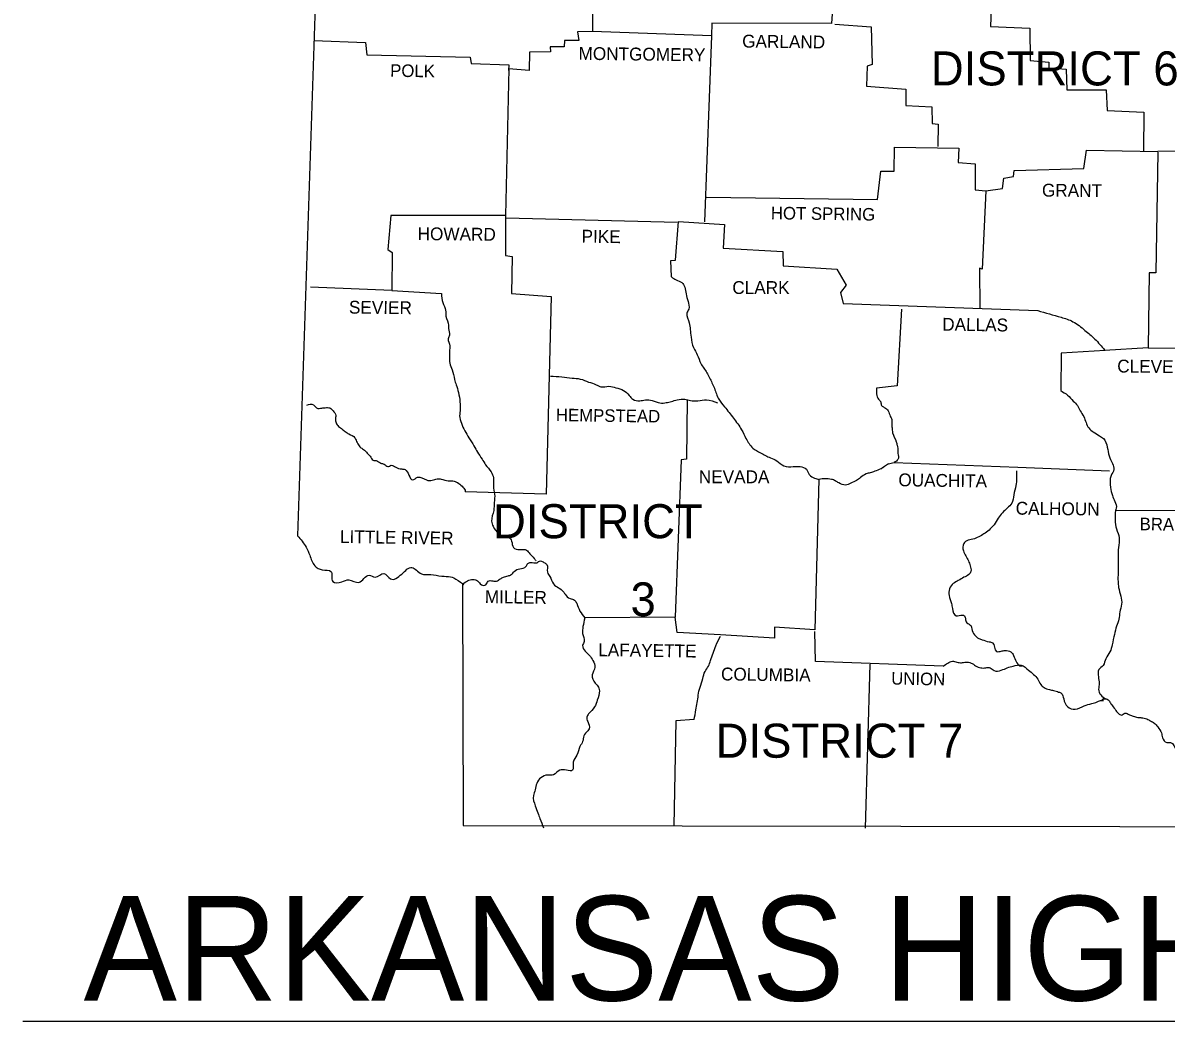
# Model space of a CAD drawing. Extents: x 155 to 3386, y 68 to 2138.
# Drawn here: x 2625.2 to 2999.8, y 1369.4 to 1696.4 of the extents above; entities that cross this region are included whole.
import ezdxf

# ---------------------------------------------------------------- set-up
doc = ezdxf.new("R2010")
doc.units = 0
for name, color, linetype in [('1', 7, 'Continuous'), ('2', 7, 'Continuous'), ('3', 7, 'Continuous')]:
    doc.layers.add(name, color=color, linetype=linetype)

msp = doc.modelspace()

# ---------------------------------------------------------------- linework, layer by layer
at = {"layer": '1'}
for points in [[(2703.71, 1956.42), (2723.96, 1793.81), (2715.15, 1528.37)], [(2812.02, 1750.86), (2811.82, 1693.62), (2806.93, 1693.52), (2807.32, 1690.59), (2802.62, 1690.68), (2802.53, 1688.53), (2797.93, 1688.53), (2798.03, 1686.97), (2791.18, 1686.77), (2791.08, 1680.8), (2784.43, 1681.39), (2783.35, 1633.25), (2745.68, 1633.35), (2744.8, 1622.19), (2746.17, 1621.22), (2746.07, 1608.69), (2719.36, 1609.87)], [(2922.97, 1707.81), (2890.97, 1708.78), (2890.09, 1696.16), (2850.96, 1696.36), (2850.76, 1692.15)], [(2931.68, 1708.1), (2942.63, 1707.41), (2942.24, 1695.18), (2955.06, 1694.69), (2955.26, 1684.03), (2961.32, 1683.54), (2961.32, 1681.68), (2967, 1681.29), (2967.19, 1674.44), (2980.11, 1674.44), (2980.5, 1667.69), (2992.44, 1667.1), (2992.34, 1654.38)], [(2850.76, 1692.15), (2811.82, 1693.62)], [(2891.27, 1695.97), (2903.11, 1695.09), (2903.5, 1682.76), (2901.83, 1682.17), (2901.64, 1675.62), (2914.46, 1674.74), (2914.46, 1669.35), (2922.97, 1668.86), (2923.07, 1663.48), (2925.12, 1663.19), (2925.02, 1655.95)], [(2720.54, 1690.59), (2737.46, 1690), (2737.85, 1685.89), (2771.71, 1685.2), (2772.1, 1683.05), (2784.43, 1682.66), (2784.33, 1680.8)], [(2850.76, 1692.15), (2848.51, 1631.2)], [(3109.06, 1665.64), (3072.08, 1666.61), (3071.88, 1654.58), (2997.03, 1654.29)], [(2849.2, 1639.32), (2905.16, 1638.53), (2906.24, 1647.83), (2910.64, 1647.83), (2910.74, 1655.66), (2931.87, 1655.36), (2931.68, 1650.67), (2937.16, 1650.27), (2937.16, 1641.66), (2940.68, 1641.37)], [(2940.68, 1641.37), (2946.16, 1642.15), (2946.55, 1645.48), (2949.78, 1646.07), (2949.97, 1648.02), (2972.77, 1648.71), (2973.65, 1654.68), (2997.03, 1654.29)], [(2997.03, 1654.09), (2996.45, 1614.56), (2994.2, 1614.47), (2993.9, 1589.91)], [(2940.68, 1641.37), (2939.5, 1615.74), (2938.62, 1616.03), (2938.72, 1602.72)], [(2783.35, 1633.25), (2783.35, 1620.24), (2785.5, 1619.85), (2785.31, 1607.71), (2798.22, 1606.74), (2796.66, 1542.06), (2770.04, 1542.75)], [(2783.55, 1632.57), (2839.51, 1631.1)], [(2837.65, 1613.19), (2837.46, 1618.57), (2839.02, 1618.67), (2840, 1631.29), (2855.07, 1630.32), (2854.68, 1622.59), (2874.15, 1621.51), (2874.24, 1616.81), (2891.85, 1615.74), (2894.89, 1610.45), (2893.03, 1608.11), (2893.91, 1604.49), (2957.7, 1602.14)], [(2746.07, 1608.69), (2762.31, 1607.71)], [(2913.09, 1602.63), (2911.62, 1577.48), (2904.87, 1576.7)], [(2979.81, 1589.03), (2965.33, 1588.15), (2965.24, 1575.92)], [(2993.9, 1589.91), (2979.62, 1589.03)], [(2993.9, 1589.91), (3028.54, 1589.71)], [(2842.84, 1572.98), (2842.64, 1553.51), (2840.88, 1553.31), (2838.92, 1501.75)], [(2910.64, 1552.34), (2951.15, 1550.87), (2981.18, 1549.69)], [(2885.98, 1546.86), (2884.71, 1497.55), (2871.5, 1498.43), (2871.41, 1494.81), (2853.79, 1495.88)], [(2983.14, 1536.68), (3027.36, 1536.78)], [(2769.26, 1512.61), (2769.46, 1433.46), (3128.04, 1432.87)], [(2853.79, 1495.88), (2839.61, 1496.67), (2838.92, 1501.75), (2809.28, 1501.46)], [(2926.69, 1485.61), (2884.91, 1487.17), (2884.71, 1497.06)], [(2902.72, 1486.29), (2901.15, 1432.58)], [(2845.18, 1468.19), (2839.12, 1467.8), (2838.43, 1433.36)]]:
    msp.add_lwpolyline(points, dxfattribs=at)
for points in [[(2837.65, 1613.19), (2839.22, 1612.21), (2841.08, 1611.33), (2842.05, 1609.87), (2842.45, 1607.62), (2843.13, 1605.17), (2843.33, 1602.63), (2842.74, 1601.26), (2843.52, 1598.13), (2843.82, 1595.97), (2844.11, 1593.43), (2844.89, 1590.01), (2846.16, 1587.66), (2847.34, 1584.82), (2849.29, 1581.79), (2850.96, 1578.46), (2851.74, 1576.7), (2853.21, 1573.08), (2855.07, 1570.63), (2858, 1566.91), (2860.64, 1563.1), (2862.11, 1560.26), (2864.36, 1557.13), (2866.91, 1555.57), (2870.13, 1553.9), (2872.19, 1552.92), (2874.54, 1551.26), (2877.57, 1551.06), (2879.82, 1551.06), (2881.88, 1550.18), (2882.85, 1548.42), (2884.61, 1547.25), (2885.98, 1546.86)], [(2762.31, 1607.71), (2762.8, 1604.78), (2763.68, 1602.24), (2763.78, 1600.28), (2764.66, 1597.34), (2764.66, 1596.27), (2764.96, 1594.11), (2764.56, 1592.94), (2765.05, 1590.59), (2764.96, 1588.83), (2764.96, 1587.36), (2765.05, 1584.92), (2765.84, 1582.76), (2766.62, 1579.54), (2767.11, 1577.87), (2767.89, 1575.33), (2768.38, 1572.2), (2768.48, 1569.85), (2768.28, 1567.7), (2768.87, 1565.25), (2769.95, 1562.81), (2771.32, 1560.46), (2772.98, 1557.82), (2774.15, 1555.76), (2775.62, 1553.51), (2776.79, 1551.65), (2778.56, 1549.3), (2779.34, 1547.35), (2779.34, 1544.61), (2779.73, 1542.06), (2779.63, 1539.23), (2779.44, 1536.68), (2778.75, 1533.16), (2779.24, 1531.5), (2781.1, 1529.05), (2782.27, 1528.37), (2784.33, 1527.97), (2785.31, 1526.6), (2785.89, 1524.55), (2787.95, 1523.86), (2790.2, 1523.67), (2791.27, 1522.49), (2792.74, 1520.93), (2793.23, 1520.15)], [(2957.7, 1602.14), (2965.33, 1599.98), (2969.25, 1598.52), (2973.16, 1595.68), (2976.39, 1592.84), (2979.62, 1589.22)], [(2798.03, 1580.71), (2801.74, 1580.42), (2805.17, 1580.03), (2807.81, 1579.73), (2810.55, 1578.75), (2813, 1577.87), (2814.56, 1577.19), (2817.2, 1577.38), (2819.45, 1576.89), (2822, 1576.01), (2823.86, 1574.35), (2825.03, 1573.08), (2827.28, 1572.59), (2829.14, 1572.88), (2831.39, 1572.69), (2833.93, 1571.9), (2835.99, 1572), (2837.65, 1572.39), (2839.61, 1572.88), (2842.05, 1573.08), (2843.91, 1572.69), (2846.36, 1572.59), (2849.2, 1572.88), (2852.72, 1571.9)], [(2904.87, 1576.7), (2904.87, 1574.84), (2905.55, 1573.08), (2906.24, 1572.3), (2906.53, 1571.02), (2907.41, 1570.44), (2908.68, 1569.26), (2909.37, 1567.6), (2909.86, 1566.52), (2909.86, 1565.15), (2909.96, 1563.78), (2910.15, 1562.12), (2911.33, 1559.19), (2911.62, 1558.01), (2911.81, 1557.03), (2911.91, 1555.37), (2911.91, 1553.41), (2910.64, 1552.34)], [(2965.24, 1575.92), (2967.49, 1574.45), (2969.34, 1572.49), (2970.71, 1571.02), (2971.59, 1569.36), (2972.77, 1567.4), (2974.43, 1563.69), (2975.9, 1562.41), (2977.95, 1561.14), (2979.23, 1560.26), (2980.5, 1557.42), (2981.09, 1554.59), (2982.16, 1552.04), (2982.65, 1550.09), (2981.77, 1548.13), (2981.57, 1544.22), (2982.16, 1541.57), (2982.94, 1539.62), (2983.43, 1537.37), (2983.14, 1536.68)], [(2718.19, 1571.22), (2720.34, 1571.32), (2721.81, 1570.05), (2722.69, 1570.14), (2724.25, 1570.34), (2725.72, 1570.24), (2726.8, 1569.36), (2727.68, 1567.8), (2727.58, 1566.33), (2727.68, 1565.74), (2728.36, 1564.47), (2729.54, 1563.49), (2730.81, 1562.51), (2731.98, 1561.73), (2733.94, 1560.46), (2734.14, 1560.07), (2734.92, 1558.5), (2735.9, 1557.23), (2737.07, 1556.45), (2738.34, 1555.08), (2738.93, 1554.49), (2739.91, 1553.12), (2740.98, 1553.02), (2742.45, 1552.14), (2743.53, 1551.85), (2744.7, 1551.06), (2745.88, 1551.46), (2747.34, 1550.87), (2749.3, 1550.28), (2750.38, 1550.09), (2751.65, 1548.23), (2752.92, 1546.66), (2754.49, 1547.54), (2757.42, 1546.66), (2759.28, 1546.56), (2760.94, 1547.05), (2762.22, 1546.96), (2764.56, 1546.37), (2766.03, 1546.37), (2767.6, 1545.78), (2769.06, 1544.61), (2770.04, 1543.34), (2770.04, 1542.75)], [(2908.78, 1551.95), (2906.24, 1550.28), (2904.28, 1549.5), (2902.81, 1549.01), (2901.44, 1548.62), (2899.68, 1547.44), (2898.31, 1546.47), (2896.45, 1545.59), (2894.69, 1545), (2892.54, 1545.68), (2891.37, 1546.37), (2890.09, 1546.86), (2885.98, 1546.86)], [(2906.24, 1550.28), (2908.78, 1551.95), (2910.64, 1552.34)], [(2950.75, 1549.69), (2950.56, 1544.8), (2949.87, 1541.77), (2949.19, 1539.03), (2947.72, 1537.46), (2946.16, 1535.9), (2944.69, 1534.14), (2943.42, 1531.99), (2942.14, 1530.62), (2940.48, 1529.25), (2938.82, 1528.27), (2936.96, 1527.39), (2934.9, 1526.9), (2933.44, 1525.82), (2933.34, 1523.47), (2935, 1520.15), (2935.59, 1518.58), (2935.79, 1516.72), (2935.1, 1515.65), (2933.53, 1514.77), (2931.68, 1513.69), (2930.01, 1512.71), (2928.84, 1511.05), (2928.64, 1508.8), (2929.43, 1506.16), (2929.72, 1504.59), (2930.99, 1502.14), (2931.97, 1502.24), (2933.73, 1502.14), (2933.93, 1501.65), (2934.02, 1501.17), (2934.42, 1499.89), (2935.88, 1498.82), (2936.08, 1497.84), (2936.96, 1495.98), (2938.43, 1494.71), (2939.5, 1494.32), (2941.75, 1493.63), (2942.93, 1493.34), (2944.2, 1490.5), (2945.77, 1490.6), (2946.94, 1490.79), (2948.9, 1490.31), (2949.78, 1489.13), (2950.66, 1487.17), (2951.83, 1485.8), (2952.61, 1485.8)], [(2983.14, 1536.68), (2983.53, 1530.62), (2984.41, 1527.68), (2984.12, 1524.55), (2984.02, 1521.52), (2984.02, 1518.78), (2984.02, 1516.14), (2984.02, 1513.4), (2984.22, 1511.44), (2984.9, 1508.6), (2985.19, 1505.96), (2984.61, 1503.42), (2984.31, 1501.07), (2983.53, 1498.72), (2982.85, 1496.08), (2982.06, 1492.65), (2981.38, 1490.4), (2980.01, 1488.06), (2979.13, 1485.9), (2977.76, 1484.53), (2977.56, 1482.18), (2977.86, 1480.03), (2977.66, 1478.08), (2978.35, 1476.22), (2980.11, 1474.94)], [(2715.15, 1528.37), (2717.99, 1524.65), (2719.17, 1522.01), (2720.83, 1518.58), (2723.28, 1517.21), (2726.11, 1516.72), (2726.7, 1513.4), (2729.63, 1513.3), (2731.98, 1513.98), (2735.21, 1513.1), (2738.64, 1515.45), (2740.59, 1514.86), (2743.43, 1516.04), (2745.58, 1514.28), (2749.3, 1515.84), (2752.63, 1517.99), (2755.76, 1515.94), (2758.79, 1515.65), (2762.41, 1515.16), (2765.25, 1514.96), (2767.79, 1513.69), (2769.65, 1512.42), (2769.26, 1512.61)], [(2769.26, 1512.61), (2772.68, 1514.08), (2774.15, 1513.59), (2775.42, 1512.32), (2776.89, 1512.32), (2777.67, 1513.49), (2779.14, 1513.59), (2780.32, 1513.49), (2781.59, 1514.28), (2782.66, 1514.77), (2784.13, 1515.25), (2785.21, 1515.65), (2786.19, 1516.72), (2787.95, 1517.6), (2790, 1518.29), (2790.59, 1519.27), (2791.57, 1519.66), (2793.52, 1519.56), (2794.8, 1520.15), (2795.87, 1519.66), (2796.85, 1518.97), (2797.05, 1516.43), (2797.83, 1515.06), (2799, 1512.61), (2800.67, 1511.34), (2802.23, 1510.07), (2802.82, 1509.29), (2804.48, 1507.82), (2805.95, 1507.33), (2806.64, 1506.25), (2807.71, 1503.71), (2809.28, 1501.46)], [(2809.28, 1501.46), (2808.69, 1498.62), (2808.59, 1496.37), (2809.08, 1493.73), (2808.59, 1492.46), (2809.38, 1490.6), (2810.84, 1489.13), (2811.92, 1487.57), (2812.6, 1485.32), (2811.72, 1482.77), (2812.7, 1480.13), (2813.58, 1479.15), (2814.07, 1477.59), (2813.39, 1474.55), (2812.51, 1472.3), (2810.55, 1470.05), (2809.96, 1468.98), (2810.26, 1467.51), (2810.74, 1465.16), (2810.26, 1464.48), (2808.98, 1462.81), (2808.59, 1460.95), (2807.71, 1459.39), (2806.73, 1456.55), (2805.46, 1454.2), (2805.27, 1451.56), (2803.31, 1451.56), (2801.06, 1451.56), (2799, 1450.09), (2797.15, 1450), (2794.89, 1449.11), (2793.52, 1447.26), (2793.04, 1445.2), (2792.45, 1443.24), (2793.04, 1439.92), (2793.92, 1437.57), (2794.6, 1435.71), (2795.78, 1432.68)], [(2845.18, 1468.19), (2845.67, 1471.32), (2846.16, 1473.77), (2846.46, 1476.12), (2847.04, 1478.76), (2847.92, 1481.6), (2848.71, 1483.95), (2849.78, 1485.61), (2850.47, 1487.57), (2851.35, 1489.91), (2852.23, 1492.36), (2853.79, 1495.49)], [(2926.69, 1485.61), (2928.25, 1486.69), (2929.72, 1487.27), (2931.19, 1486.98), (2932.75, 1486.78), (2934.12, 1486.98), (2935.88, 1486.69), (2937.35, 1485.8), (2939.01, 1485.12), (2940.68, 1485.12), (2942.14, 1485.12), (2943.42, 1484.24), (2945.77, 1484.34), (2947.72, 1485.12), (2949.68, 1485.71), (2952.32, 1486), (2954.67, 1484.34), (2956.33, 1482.97), (2957.7, 1481.4), (2958.68, 1479.64), (2959.76, 1478.66), (2961.52, 1477.98), (2962.89, 1477.68), (2964.55, 1477.19), (2965.43, 1476.8), (2966.21, 1474.94), (2967.49, 1472.4), (2969.93, 1471.52), (2972.96, 1472.69), (2975.41, 1473.38), (2977.17, 1473.97), (2978.25, 1474.36), (2979.23, 1474.46), (2978.93, 1474.65), (2980.11, 1474.94), (2981.18, 1474.16), (2981.87, 1473.09), (2983.04, 1471.52), (2984.12, 1470.15), (2985.19, 1469.66), (2986.27, 1470.25), (2987.74, 1469.76), (2989.01, 1469.27), (2990.48, 1468.88), (2991.75, 1468.78), (2993.41, 1468.39), (2994.69, 1467.7), (2995.86, 1467.02), (2997.03, 1465.75), (2998.21, 1463.79), (2998.6, 1462.23), (2999.97, 1460.66), (3001.24, 1460.66), (3003.1, 1458.12), (3003.78, 1457.14), (3005.25, 1455.38), (3006.33, 1455.38), (3008.38, 1454.98)]]:
    msp.add_spline(points, degree=3, dxfattribs=at)
at = {"layer": '2'}
msp.add_line((2625.16, 1369.37), (3289.7, 1369.37), dxfattribs=at)

# ---------------------------------------------------------------- texts
for s, height, rotation, p in [('GARLAND', 4.207, 359.3658, (2860.84, 1688.33)), ('MONTGOMERY', 4.207, 359.2944, (2807.22, 1684.32)), ('POLK', 4.108, 359.2152, (2745.49, 1678.75)), ('GRANT', 4.207, 359.4032, (2959.07, 1639.51)), ('HOT SPRING', 4.109, 359.2216, (2870.23, 1632.08)), ('HOWARD', 4.207, 359.5145, (2754.49, 1625.23)), ('PIKE', 4.206, 359.0452, (2808.2, 1624.44)), ('SEVIER', 4.207, 359.4271, (2731.98, 1601.16)), ('DALLAS', 4.206, 359.2462, (2926.39, 1595.58)), ('CLEVELAND', 4.207, 359.3377, (2983.73, 1581.88)), ('HEMPSTEAD', 4.108, 359.1885, (2799.79, 1565.94)), ('OUACHITA', 4.207, 359.2043, (2912.01, 1544.61)), ('CALHOUN', 4.207, 359.3634, (2950.46, 1535.31)), ('BRADLEY', 4.108, 359.1449, (2991.07, 1530.22)), ('LITTLE RIVER', 4.2073, 359.1697, (2729.05, 1526.02)), ('MILLER', 4.206, 359.1319, (2776.5, 1506.35)), ('LAFAYETTE', 4.206, 359.1839, (2813.68, 1488.94)), ('COLUMBIA', 4.206, 359.2125, (2853.89, 1481.01)), ('UNION', 4.109, 358.9584, (2909.66, 1479.64))]:
    msp.add_text(s, height=height, rotation=rotation, dxfattribs=at).set_placement(p)
for s, height, p in [('CLARK', 4.207, (2857.63, 1607.59)), ('NEVADA', 4.207, (2846.65, 1545.59)), ('ARKANSAS HIGHWAY DISTRICT 1', 34.244, (2645.08, 1376.13))]:
    msp.add_text(s, height=height, dxfattribs=at).set_placement(p)
at = {"layer": '3'}
for s, height, p in [('DISTRICT 6', 11.154, (2922.67, 1675.91)), ('DISTRICT', 11.154, (2779.19, 1527.57)), ('3', 11.06, (2824.3, 1502.04)), ('DISTRICT 7', 11.154, (2852.13, 1455.67))]:
    msp.add_text(s, height=height, dxfattribs=at).set_placement(p)

doc.saveas('drawing.dxf')
